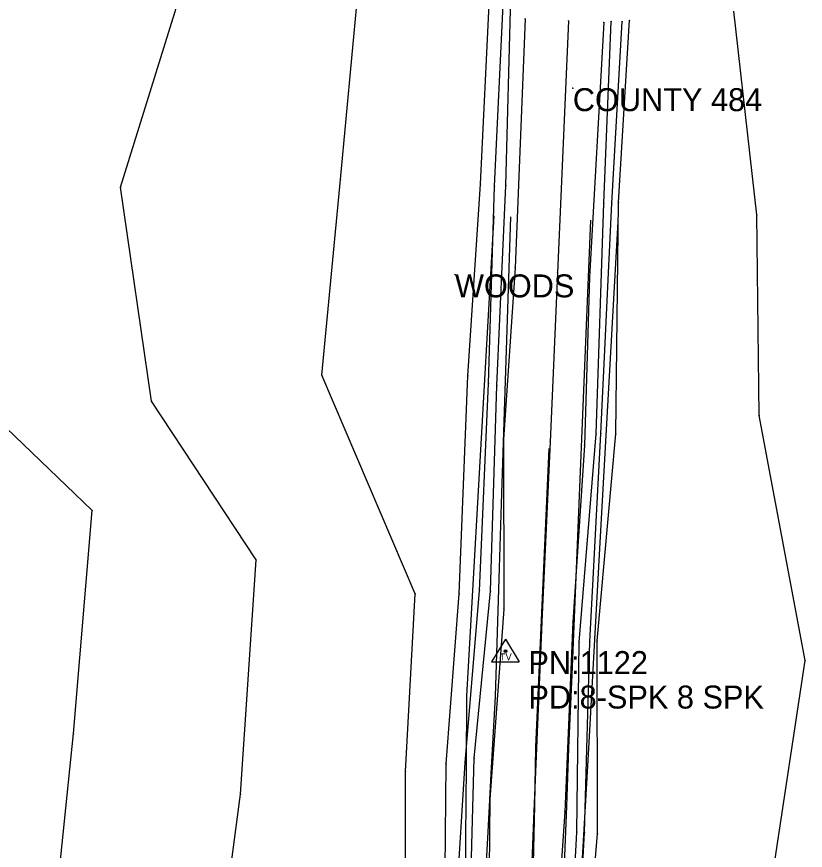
# Model space of a CAD drawing. Extents: x 976456 to 985170, y 1525951 to 1527080.
# Drawn here: x 978253.9 to 978425.6, y 1526718.6 to 1526900 of the extents above; entities that cross this region are included whole.
import ezdxf

# ---------------------------------------------------------------- set-up
doc = ezdxf.new("R2010")
doc.units = 0
for name, color, linetype in [('S_BREAKLINE', 7, 'Continuous'), ('S_DITCHLINE', 7, 'Continuous'), ('S_GRAVEL_ROAD', 7, 'Continuous'), ('S_GRD_PT_SYM', 7, 'Continuous'), ('S_MSC_PT_SYM', 7, 'Continuous'), ('S_PAVEMENT_CROWN', 7, 'Continuous'), ('S_RDW_PT_SYM', 7, 'Continuous'), ('S_SECONDARY_CTL', 7, 'Continuous'), ('S_SECONDARY_CTL_ANNOT', 7, 'Continuous'), ('S_SURVEY_TEXT_ANNOT', 7, 'Continuous')]:
    doc.layers.add(name, color=color, linetype=linetype)

msp = doc.modelspace()

# ---------------------------------------------------------------- linework, layer by layer
at = {"layer": 'S_BREAKLINE'}
for p, q in [((978324.37, 1526864.63), (978328.52, 1526909.37)), ((978276.43, 1526862.9), (978289.99, 1526906.34)), ((978354.87, 1526863.6), (978356.9, 1526905.79)), ((978415.03, 1526856.89), (978410.02, 1526901.26)), ((978384.9, 1526859.6), (978387.34, 1526899.24)), ((978320.31, 1526822.02), (978324.37, 1526864.63)), ((978352.12, 1526821.86), (978354.87, 1526863.6)), ((978283.25, 1526816.38), (978276.43, 1526862.9)), ((978384.32, 1526809.23), (978384.9, 1526859.6)), ((978415.58, 1526813.24), (978415.03, 1526856.89)), ((978340.63, 1526774.42), (978320.31, 1526822.02)), ((978350.22, 1526774.42), (978352.12, 1526821.86)), ((978306.03, 1526781.79), (978283.25, 1526816.38)), ((978270.31, 1526792.58), (978245.87, 1526816.01)), ((978425.55, 1526759.95), (978415.58, 1526813.24)), ((978380.24, 1526764.18), (978384.32, 1526809.23)), ((978266.24, 1526744), (978270.31, 1526792.58)), ((978302.57, 1526730.84), (978306.03, 1526781.79)), ((978338.52, 1526735.78), (978340.63, 1526774.42)), ((978347.36, 1526737.43), (978350.22, 1526774.42)), ((978380.33, 1526722.25), (978380.24, 1526764.18)), ((978418.68, 1526714.25), (978425.55, 1526759.95)), ((978261.62, 1526699.5), (978266.24, 1526744)), ((978347.1, 1526708.43), (978347.36, 1526737.43)), ((978338.52, 1526709.56), (978338.52, 1526735.78)), ((978299.32, 1526706.1), (978302.57, 1526730.84)), ((978376.24, 1526673.84), (978380.33, 1526722.25))]:
    msp.add_line(p, q, dxfattribs=at)
at = {"layer": 'S_DITCHLINE'}
for p, q in [((978357.92, 1526863.11), (978359.94, 1526905.05)), ((978360.37, 1526863.28), (978361.45, 1526904.9)), ((978381.74, 1526859.43), (978383.3, 1526898.97)), ((978383.44, 1526859.46), (978385.73, 1526898.98)), ((978356.58, 1526820.19), (978357.92, 1526863.11)), ((978358.41, 1526819.8), (978360.37, 1526863.28)), ((978380.05, 1526809.21), (978381.74, 1526859.43)), ((978381.05, 1526809.32), (978383.44, 1526859.46)), ((978354.65, 1526775.1), (978356.58, 1526820.19)), ((978357.02, 1526774.98), (978358.41, 1526819.8)), ((978376.38, 1526763.94), (978380.05, 1526809.21)), ((978378.68, 1526764.01), (978381.05, 1526809.32)), ((978351.5, 1526737.72), (978354.65, 1526775.1)), ((978353.45, 1526738.65), (978357.02, 1526774.98)), ((978375.84, 1526722.59), (978376.38, 1526763.94)), ((978377.5, 1526722.48), (978378.68, 1526764.01)), ((978352.68, 1526708.2), (978353.45, 1526738.65)), ((978349.66, 1526708.4), (978351.5, 1526737.72)), ((978373.17, 1526673.71), (978375.84, 1526722.59)), ((978374.89, 1526673.66), (978377.5, 1526722.48))]:
    msp.add_line(p, q, dxfattribs=at)
for points in [[(978357.79, 1526856.67), (978354.22, 1526794.28), (978353.42, 1526780.26), (978352.61, 1526766.23), (978351.81, 1526752.21), (978351.72, 1526736.82), (978351.62, 1526721.44), (978351.53, 1526706.05), (978351.43, 1526690.66), (978351.15, 1526670.64), (978350.87, 1526650.61), (978349.73, 1526630.64), (978348.6, 1526610.67), (978347.67, 1526588.4), (978339.7, 1526577.91), (978334.68, 1526574.46), (978319.32, 1526573.81), (978303.97, 1526573.16), (978288.62, 1526572.51), (978273.26, 1526571.86)], [(978372.35, 1526582.55), (978372.7, 1526603.74), (978373.04, 1526624.94), (978373.67, 1526641.3), (978374.3, 1526657.67), (978374.93, 1526674.03), (978375.55, 1526690.4), (978376.27, 1526702.99), (978376.99, 1526715.58), (978377.71, 1526728.18), (978378.43, 1526740.77), (978379.31, 1526756.58), (978380.19, 1526772.4), (978381.08, 1526788.21), (978384.83, 1526855.41)]]:
    msp.add_lwpolyline(points, dxfattribs=at)
at = {"layer": 'S_GRAVEL_ROAD'}
for p, q in [((978364.62, 1526899.56), (978362.43, 1526845.38)), ((978381.69, 1526898.76), (978378.63, 1526843.37)), ((978362.43, 1526845.38), (978359.88, 1526808)), ((978378.63, 1526843.37), (978377.48, 1526806.78)), ((978359.88, 1526808), (978359.93, 1526771.11)), ((978377.48, 1526806.78), (978374.95, 1526768.24)), ((978359.93, 1526771.11), (978356.93, 1526729.73)), ((978374.95, 1526768.24), (978373.23, 1526726.99)), ((978356.93, 1526729.73), (978356.58, 1526700.86)), ((978373.23, 1526726.99), (978371.2, 1526696.72))]:
    msp.add_line(p, q, dxfattribs=at)
for points in [[(978361.37, 1526856.47), (978359.38, 1526794.04), (978358.93, 1526780.06), (978358.49, 1526766.07), (978358.04, 1526752.09), (978357.2, 1526736.65), (978356.36, 1526721.22), (978355.52, 1526705.79), (978354.68, 1526690.35), (978354.79, 1526670.11), (978354.9, 1526649.86), (978352.93, 1526629.69), (978350.96, 1526609.51), (978349.95, 1526587.81), (978348.71, 1526571.32), (978347.48, 1526554.83), (978344.69, 1526542.11), (978341.91, 1526529.4), (978336.32, 1526519.7), (978328.9, 1526510.25)], [(978381.06, 1526508.64), (978369.53, 1526517.1), (978368.86, 1526529.94), (978368.19, 1526542.79), (978368.22, 1526555.92), (978368.26, 1526569.05), (978369.23, 1526584.52), (978369.8, 1526604.85), (978370.36, 1526625.19), (978370.83, 1526641.45), (978371.3, 1526657.71), (978371.76, 1526673.97), (978372.23, 1526690.23), (978372.7, 1526702.89), (978373.18, 1526715.55), (978373.65, 1526728.21), (978374.13, 1526740.87), (978374.79, 1526756.83), (978375.46, 1526772.79), (978376.12, 1526788.75), (978378.92, 1526855.74)]]:
    msp.add_lwpolyline(points, dxfattribs=at)
at = {"layer": 'S_GRD_PT_SYM'}
for points in [[(978383.3, 1526898.97), (978383.3, 1526899.02), (978383.3, 1526898.97), (978383.25, 1526898.97), (978383.3, 1526898.97), (978383.3, 1526898.92), (978383.3, 1526898.97), (978383.35, 1526898.97)], [(978385.73, 1526898.98), (978385.73, 1526899.03), (978385.73, 1526898.98), (978385.68, 1526898.98), (978385.73, 1526898.98), (978385.73, 1526898.93), (978385.73, 1526898.98), (978385.78, 1526898.98)], [(978387.34, 1526899.24), (978387.34, 1526899.29), (978387.34, 1526899.24), (978387.29, 1526899.24), (978387.34, 1526899.24), (978387.34, 1526899.19), (978387.34, 1526899.24), (978387.39, 1526899.24)], [(978324.37, 1526864.63), (978324.37, 1526864.68), (978324.37, 1526864.63), (978324.32, 1526864.63), (978324.37, 1526864.63), (978324.37, 1526864.58), (978324.37, 1526864.63), (978324.42, 1526864.63)], [(978354.87, 1526863.6), (978354.87, 1526863.65), (978354.87, 1526863.6), (978354.82, 1526863.6), (978354.87, 1526863.6), (978354.87, 1526863.55), (978354.87, 1526863.6), (978354.92, 1526863.6)], [(978276.43, 1526862.9), (978276.43, 1526862.95), (978276.43, 1526862.9), (978276.38, 1526862.9), (978276.43, 1526862.9), (978276.43, 1526862.85), (978276.43, 1526862.9), (978276.48, 1526862.9)], [(978357.92, 1526863.11), (978357.92, 1526863.16), (978357.92, 1526863.11), (978357.87, 1526863.11), (978357.92, 1526863.11), (978357.92, 1526863.06), (978357.92, 1526863.11), (978357.97, 1526863.11)], [(978360.37, 1526863.28), (978360.37, 1526863.33), (978360.37, 1526863.28), (978360.32, 1526863.28), (978360.37, 1526863.28), (978360.37, 1526863.23), (978360.37, 1526863.28), (978360.42, 1526863.28)], [(978381.74, 1526859.43), (978381.74, 1526859.48), (978381.74, 1526859.43), (978381.69, 1526859.43), (978381.74, 1526859.43), (978381.74, 1526859.38), (978381.74, 1526859.43), (978381.79, 1526859.43)], [(978383.44, 1526859.46), (978383.44, 1526859.51), (978383.44, 1526859.46), (978383.39, 1526859.46), (978383.44, 1526859.46), (978383.44, 1526859.41), (978383.44, 1526859.46), (978383.49, 1526859.46)], [(978384.9, 1526859.6), (978384.9, 1526859.65), (978384.9, 1526859.6), (978384.85, 1526859.6), (978384.9, 1526859.6), (978384.9, 1526859.55), (978384.9, 1526859.6), (978384.95, 1526859.6)], [(978415.03, 1526856.89), (978415.03, 1526856.94), (978415.03, 1526856.89), (978414.98, 1526856.89), (978415.03, 1526856.89), (978415.03, 1526856.84), (978415.03, 1526856.89), (978415.08, 1526856.89)], [(978320.31, 1526822.02), (978320.31, 1526822.07), (978320.31, 1526822.02), (978320.26, 1526822.02), (978320.31, 1526822.02), (978320.31, 1526821.97), (978320.31, 1526822.02), (978320.36, 1526822.02)], [(978352.12, 1526821.86), (978352.12, 1526821.91), (978352.12, 1526821.86), (978352.07, 1526821.86), (978352.12, 1526821.86), (978352.12, 1526821.81), (978352.12, 1526821.86), (978352.17, 1526821.86)], [(978356.58, 1526820.19), (978356.58, 1526820.24), (978356.58, 1526820.19), (978356.53, 1526820.19), (978356.58, 1526820.19), (978356.58, 1526820.14), (978356.58, 1526820.19), (978356.63, 1526820.19)], [(978358.41, 1526819.8), (978358.41, 1526819.85), (978358.41, 1526819.8), (978358.36, 1526819.8), (978358.41, 1526819.8), (978358.41, 1526819.75), (978358.41, 1526819.8), (978358.46, 1526819.8)], [(978283.25, 1526816.38), (978283.25, 1526816.43), (978283.25, 1526816.38), (978283.2, 1526816.38), (978283.25, 1526816.38), (978283.25, 1526816.33), (978283.25, 1526816.38), (978283.3, 1526816.38)], [(978415.58, 1526813.24), (978415.58, 1526813.29), (978415.58, 1526813.24), (978415.53, 1526813.24), (978415.58, 1526813.24), (978415.58, 1526813.19), (978415.58, 1526813.24), (978415.63, 1526813.24)], [(978380.05, 1526809.21), (978380.05, 1526809.26), (978380.05, 1526809.21), (978380, 1526809.21), (978380.05, 1526809.21), (978380.05, 1526809.16), (978380.05, 1526809.21), (978380.1, 1526809.21)], [(978381.05, 1526809.32), (978381.05, 1526809.37), (978381.05, 1526809.32), (978380.99, 1526809.32), (978381.05, 1526809.32), (978381.05, 1526809.27), (978381.05, 1526809.32), (978381.1, 1526809.32)], [(978384.32, 1526809.23), (978384.32, 1526809.28), (978384.32, 1526809.23), (978384.27, 1526809.23), (978384.32, 1526809.23), (978384.32, 1526809.18), (978384.32, 1526809.23), (978384.37, 1526809.23)], [(978270.31, 1526792.58), (978270.31, 1526792.63), (978270.31, 1526792.58), (978270.26, 1526792.58), (978270.31, 1526792.58), (978270.31, 1526792.53), (978270.31, 1526792.58), (978270.36, 1526792.58)], [(978306.03, 1526781.79), (978306.03, 1526781.84), (978306.03, 1526781.79), (978305.98, 1526781.79), (978306.03, 1526781.79), (978306.03, 1526781.74), (978306.03, 1526781.79), (978306.08, 1526781.79)], [(978340.63, 1526774.42), (978340.63, 1526774.47), (978340.63, 1526774.42), (978340.58, 1526774.42), (978340.63, 1526774.42), (978340.63, 1526774.37), (978340.63, 1526774.42), (978340.68, 1526774.42)], [(978350.22, 1526774.42), (978350.22, 1526774.47), (978350.22, 1526774.42), (978350.17, 1526774.42), (978350.22, 1526774.42), (978350.22, 1526774.37), (978350.22, 1526774.42), (978350.27, 1526774.42)], [(978354.65, 1526775.1), (978354.65, 1526775.15), (978354.65, 1526775.1), (978354.6, 1526775.1), (978354.65, 1526775.1), (978354.65, 1526775.05), (978354.65, 1526775.1), (978354.7, 1526775.1)], [(978357.02, 1526774.98), (978357.02, 1526775.03), (978357.02, 1526774.98), (978356.97, 1526774.98), (978357.02, 1526774.98), (978357.02, 1526774.93), (978357.02, 1526774.98), (978357.07, 1526774.98)], [(978376.38, 1526763.94), (978376.38, 1526763.99), (978376.38, 1526763.94), (978376.33, 1526763.94), (978376.38, 1526763.94), (978376.38, 1526763.89), (978376.38, 1526763.94), (978376.43, 1526763.94)], [(978378.68, 1526764.01), (978378.68, 1526764.06), (978378.68, 1526764.01), (978378.63, 1526764.01), (978378.68, 1526764.01), (978378.68, 1526763.96), (978378.68, 1526764.01), (978378.73, 1526764.01)], [(978380.24, 1526764.18), (978380.24, 1526764.23), (978380.24, 1526764.18), (978380.19, 1526764.18), (978380.24, 1526764.18), (978380.24, 1526764.13), (978380.24, 1526764.18), (978380.29, 1526764.18)], [(978425.55, 1526759.95), (978425.55, 1526760), (978425.55, 1526759.95), (978425.5, 1526759.95), (978425.55, 1526759.95), (978425.55, 1526759.9), (978425.55, 1526759.95), (978425.6, 1526759.95)], [(978266.24, 1526744), (978266.24, 1526744.05), (978266.24, 1526744), (978266.19, 1526744), (978266.24, 1526744), (978266.24, 1526743.95), (978266.24, 1526744), (978266.29, 1526744)], [(978353.45, 1526738.65), (978353.45, 1526738.7), (978353.45, 1526738.65), (978353.4, 1526738.65), (978353.45, 1526738.65), (978353.45, 1526738.6), (978353.45, 1526738.65), (978353.5, 1526738.65)], [(978347.36, 1526737.43), (978347.36, 1526737.48), (978347.36, 1526737.43), (978347.31, 1526737.43), (978347.36, 1526737.43), (978347.36, 1526737.38), (978347.36, 1526737.43), (978347.41, 1526737.43)], [(978351.5, 1526737.72), (978351.5, 1526737.77), (978351.5, 1526737.72), (978351.45, 1526737.72), (978351.5, 1526737.72), (978351.5, 1526737.67), (978351.5, 1526737.72), (978351.55, 1526737.72)], [(978338.52, 1526735.78), (978338.52, 1526735.83), (978338.52, 1526735.78), (978338.47, 1526735.78), (978338.52, 1526735.78), (978338.52, 1526735.73), (978338.52, 1526735.78), (978338.57, 1526735.78)], [(978302.57, 1526730.84), (978302.57, 1526730.89), (978302.57, 1526730.84), (978302.52, 1526730.84), (978302.57, 1526730.84), (978302.57, 1526730.79), (978302.57, 1526730.84), (978302.62, 1526730.84)], [(978375.84, 1526722.59), (978375.84, 1526722.64), (978375.84, 1526722.59), (978375.79, 1526722.59), (978375.84, 1526722.59), (978375.84, 1526722.54), (978375.84, 1526722.59), (978375.89, 1526722.59)], [(978377.5, 1526722.48), (978377.5, 1526722.53), (978377.5, 1526722.48), (978377.45, 1526722.48), (978377.5, 1526722.48), (978377.5, 1526722.43), (978377.5, 1526722.48), (978377.55, 1526722.48)], [(978380.33, 1526722.25), (978380.33, 1526722.3), (978380.33, 1526722.25), (978380.28, 1526722.25), (978380.33, 1526722.25), (978380.33, 1526722.2), (978380.33, 1526722.25), (978380.38, 1526722.25)]]:
    msp.add_lwpolyline(points, dxfattribs=at)
at = {"layer": 'S_MSC_PT_SYM'}
for points in [[(978374.97, 1526884.47), (978374.97, 1526884.52), (978374.97, 1526884.47), (978374.92, 1526884.47), (978374.97, 1526884.47), (978374.97, 1526884.42), (978374.97, 1526884.47), (978375.02, 1526884.47)], [(978349.3, 1526843.94), (978349.3, 1526843.99), (978349.3, 1526843.94), (978349.25, 1526843.94), (978349.3, 1526843.94), (978349.3, 1526843.89), (978349.3, 1526843.94), (978349.35, 1526843.94)]]:
    msp.add_lwpolyline(points, dxfattribs=at)
at = {"layer": 'S_PAVEMENT_CROWN'}
for p, q in [((978374.05, 1526899.16), (978371.64, 1526844.3)), ((978371.64, 1526844.3), (978370, 1526807.54)), ((978370, 1526807.54), (978368.26, 1526769.97)), ((978368.26, 1526769.97), (978366.45, 1526727.14)), ((978366.45, 1526727.14), (978365.38, 1526699.89))]:
    msp.add_line(p, q, dxfattribs=at)
msp.add_lwpolyline([(978356.9, 1526508.47), (978357.57, 1526527.13), (978358.24, 1526545.8), (978359.35, 1526558.49), (978360.47, 1526571.19), (978360.67, 1526585.26), (978361.11, 1526605.62), (978361.56, 1526625.97), (978362.65, 1526642.09), (978363.74, 1526658.21), (978364.83, 1526674.33), (978365.92, 1526690.45), (978366.17, 1526703.09), (978366.42, 1526715.74), (978366.67, 1526728.38), (978366.92, 1526741.02), (978367.64, 1526757.28), (978368.35, 1526773.54), (978369.07, 1526789.8), (978369.78, 1526806.07)], dxfattribs=at)
at = {"layer": 'S_RDW_PT_SYM'}
for points in [[(978364.62, 1526899.56), (978364.62, 1526899.61), (978364.62, 1526899.56), (978364.57, 1526899.56), (978364.62, 1526899.56), (978364.62, 1526899.51), (978364.62, 1526899.56), (978364.67, 1526899.56)], [(978374.05, 1526899.16), (978374.05, 1526899.21), (978374.05, 1526899.16), (978374, 1526899.16), (978374.05, 1526899.16), (978374.05, 1526899.11), (978374.05, 1526899.16), (978374.1, 1526899.16)], [(978381.69, 1526898.76), (978381.69, 1526898.81), (978381.69, 1526898.76), (978381.64, 1526898.76), (978381.69, 1526898.76), (978381.69, 1526898.71), (978381.69, 1526898.76), (978381.74, 1526898.76)], [(978362.43, 1526845.38), (978362.43, 1526845.43), (978362.43, 1526845.38), (978362.38, 1526845.38), (978362.43, 1526845.38), (978362.43, 1526845.33), (978362.43, 1526845.38), (978362.48, 1526845.38)], [(978371.64, 1526844.3), (978371.64, 1526844.35), (978371.64, 1526844.3), (978371.59, 1526844.3), (978371.64, 1526844.3), (978371.64, 1526844.25), (978371.64, 1526844.3), (978371.69, 1526844.3)], [(978378.63, 1526843.37), (978378.63, 1526843.42), (978378.63, 1526843.37), (978378.58, 1526843.37), (978378.63, 1526843.37), (978378.63, 1526843.32), (978378.63, 1526843.37), (978378.68, 1526843.37)], [(978359.88, 1526808), (978359.88, 1526808.05), (978359.88, 1526808), (978359.83, 1526808), (978359.88, 1526808), (978359.88, 1526807.95), (978359.88, 1526808), (978359.93, 1526808)], [(978370, 1526807.54), (978370, 1526807.59), (978370, 1526807.54), (978369.95, 1526807.54), (978370, 1526807.54), (978370, 1526807.49), (978370, 1526807.54), (978370.05, 1526807.54)], [(978377.48, 1526806.78), (978377.48, 1526806.83), (978377.48, 1526806.78), (978377.43, 1526806.78), (978377.48, 1526806.78), (978377.48, 1526806.73), (978377.48, 1526806.78), (978377.54, 1526806.78)], [(978359.93, 1526771.11), (978359.93, 1526771.16), (978359.93, 1526771.11), (978359.88, 1526771.11), (978359.93, 1526771.11), (978359.93, 1526771.06), (978359.93, 1526771.11), (978359.98, 1526771.11)], [(978368.26, 1526769.97), (978368.26, 1526770.02), (978368.26, 1526769.97), (978368.21, 1526769.97), (978368.26, 1526769.97), (978368.26, 1526769.92), (978368.26, 1526769.97), (978368.31, 1526769.97)], [(978374.95, 1526768.24), (978374.95, 1526768.29), (978374.95, 1526768.24), (978374.9, 1526768.24), (978374.95, 1526768.24), (978374.95, 1526768.19), (978374.95, 1526768.24), (978375, 1526768.24)], [(978356.93, 1526729.73), (978356.93, 1526729.78), (978356.93, 1526729.73), (978356.88, 1526729.73), (978356.93, 1526729.73), (978356.93, 1526729.68), (978356.93, 1526729.73), (978356.98, 1526729.73)], [(978366.45, 1526727.14), (978366.45, 1526727.19), (978366.45, 1526727.14), (978366.39, 1526727.14), (978366.45, 1526727.14), (978366.45, 1526727.09), (978366.45, 1526727.14), (978366.49, 1526727.14)], [(978373.23, 1526726.99), (978373.23, 1526727.04), (978373.23, 1526726.99), (978373.18, 1526726.99), (978373.23, 1526726.99), (978373.23, 1526726.94), (978373.23, 1526726.99), (978373.28, 1526726.99)]]:
    msp.add_lwpolyline(points, dxfattribs=at)
at = {"layer": 'S_SECONDARY_CTL'}
for p, q in [((978360.3, 1526764.57), (978357.29, 1526759.61)), ((978360.3, 1526764.57), (978363.25, 1526759.61)), ((978357.29, 1526759.61), (978363.25, 1526759.61))]:
    msp.add_line(p, q, dxfattribs=at)
for radius in [0.311, 0.183, 0.103]:
    msp.add_circle((978360.3, 1526761.96), radius, dxfattribs=at)

# ---------------------------------------------------------------- texts
msp.add_text('TV', height=1.5, rotation=360, dxfattribs=at).set_placement((978359.09, 1526759.95))
at = {"layer": 'S_SECONDARY_CTL_ANNOT'}
for s, p in [('PN:1122', (978365.3, 1526756.96)), ('PD:8-SPK 8 SPK', (978365.3, 1526749.46))]:
    msp.add_text(s, height=5, dxfattribs=at).set_placement(p)
at = {"layer": 'S_SURVEY_TEXT_ANNOT'}
for s, p in [('COUNTY 484', (978374.97, 1526879.47)), ('WOODS', (978349.3, 1526838.94))]:
    msp.add_text(s, height=5, dxfattribs=at).set_placement(p)

doc.saveas('drawing.dxf')
